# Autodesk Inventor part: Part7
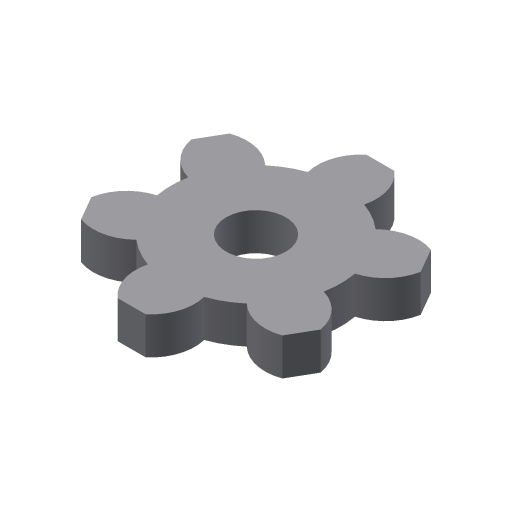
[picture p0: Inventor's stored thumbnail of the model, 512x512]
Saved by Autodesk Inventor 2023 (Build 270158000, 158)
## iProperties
Created: 2002-01
Part Number: Part7
Document SubType Name: Modeling
Designer: ***
Density: 1 g/cm^3
Material: Generic
Appearance: Default
Control State: 0
Master: False
Checked Out: False
Shininess: 77.0
Angle Display Precision: 2
Document Length Units: 11269
Document Angle Units: 11279
Document Time Units: 11290
Document Mass Units: 11283
Document Length Units Precision: 3
Document Angle Units Precision: 2
Density: 0.0
Volumn: 0.0
Area: 0.0
PropertySet Name: Model Information
Author: ***
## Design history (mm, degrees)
sketch "Sketch1"
  geometry: L1 (-3.771, 33.333)-(3.771, 33.333); L2 (-30.753, 13.401)-(-26.982, 19.933); L3 (-30.753, -13.401)-(-26.982, -19.933); L4 (-3.771, -33.333)-(3.771, -33.333); L5 (30.753, 13.401)-(26.982, 19.933); L6 (30.753, -13.401)-(26.982, -19.933); C1 r 8 at (0, 0); A1 r 11.863 centre (3.952, 24.328) between (-3.771, 33.333) and (-7.559, 21.457); A2 r 11.863 centre (-3.952, 24.328) between (7.559, 21.457) and (3.771, 33.333); A3 r 11.863 centre (-19.093, 15.587) between (-30.753, 13.401) and (-22.362, 4.182); A4 r 11.863 centre (-23.045, 8.742) between (-14.803, 17.275) and (-26.982, 19.933); A5 r 22.749 centre (0, 0) between (-7.559, 21.457) and (-14.803, 17.275); A6 r 11.863 centre (-23.045, -8.742) between (-26.982, -19.933) and (-14.803, -17.275); A7 r 11.863 centre (-19.093, -15.587) between (-22.362, -4.182) and (-30.753, -13.401); A8 r 11.863 centre (3.952, -24.328) between (-7.559, -21.457) and (-3.771, -33.333); A9 r 11.863 centre (-3.952, -24.328) between (3.771, -33.333) and (7.559, -21.457); A10 r 11.863 centre (23.045, 8.742) between (26.982, 19.933) and (14.803, 17.275); A11 r 11.863 centre (19.093, 15.587) between (22.362, 4.182) and (30.753, 13.401); A12 r 11.863 centre (19.093, -15.587) between (30.753, -13.401) and (22.362, -4.182); A13 r 11.863 centre (23.045, -8.742) between (14.803, -17.275) and (26.982, -19.933); A14 r 22.749 centre (0, 0) between (-22.362, 4.182) and (-22.362, -4.182); A15 r 22.749 centre (0, 0) between (-14.803, -17.275) and (-7.559, -21.457); A16 r 22.749 centre (0, 0) between (7.559, -21.457) and (14.803, -17.275); A17 r 22.749 centre (0, 0) between (22.362, -4.182) and (22.362, 4.182); A18 r 22.749 centre (0, 0) between (14.803, 17.275) and (7.559, 21.457)
  constraints: 36 point on circle, 19 centre point, 12 end point, 1 coincident
  dimensions: "d2" = 16 diameter of C1
extrude "Extrusion1" new body sketch "Sketch1" distance "d0" = 10; taper "d1" = 0 deg
body "Solid1"
